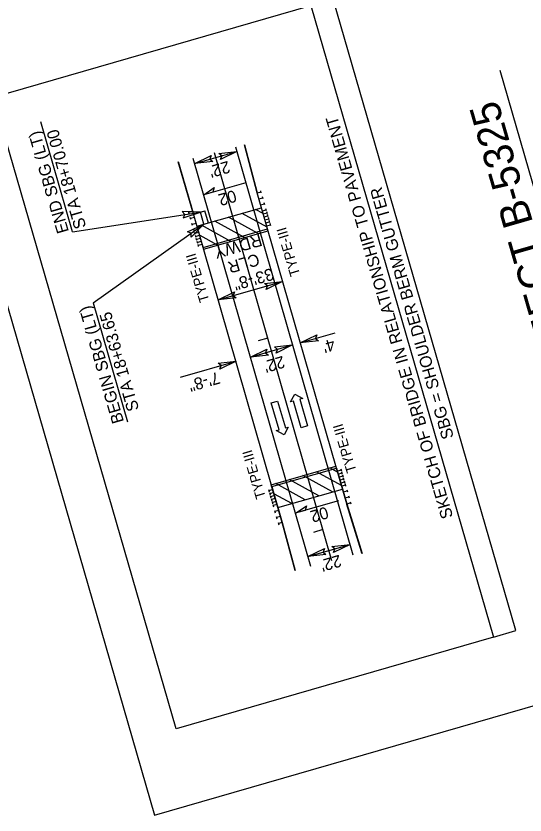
# Model space of a CAD drawing. Extents: x 2167182 to 2168576, y 842635 to 844493.
# Drawn here: x 2167498 to 2167753.4, y 842716.2 to 843117.4 of the extents above; entities that cross this region are included whole.
import ezdxf

# ---------------------------------------------------------------- set-up
doc = ezdxf.new("R2010")
doc.units = 0
for name, color, linetype in [('Old_Level_2', 7, 'Continuous'), ('Prop Approach Slab', 7, 'Continuous'), ('Prop Approach Slab Hatching', 7, 'Continuous'), ('Prop Conc Shoulder Berm Gutter', 7, 'Continuous'), ('Prop Dimension', 7, 'Continuous'), ('Prop Dimension Text', 7, 'Continuous'), ('Prop EOT', 7, 'Continuous'), ('Prop Guardrail', 7, 'Continuous'), ('Prop Horizontal Alignment', 7, 'Continuous'), ('Prop Horizontal Alignment Tick Small', 7, 'Continuous'), ('Prop Lane Arrow CELL', 7, 'Continuous'), ('Prop Paved Shoulder', 7, 'Continuous'), ('Prop Roadway Bridge', 7, 'Continuous'), ('Prop Structure Anchor Unit CELL', 7, 'Continuous'), ('Prop Superelevation  Arrow CELL', 7, 'Continuous'), ('Prop Superelevation Label', 7, 'Continuous'), ('Prop Terminator CELL', 7, 'Continuous'), ('Sheet Layout Plan Border', 7, 'Continuous')]:
    doc.layers.add(name, color=color, linetype=linetype)

msp = doc.modelspace()

# ---------------------------------------------------------------- linework, layer by layer
at = {"layer": 'Prop Approach Slab'}
for p, q in [((2167588.77, 843011.83), (2167621.12, 843021.13)), ((2167588.77, 843011.83), (2167592.08, 843000.29)), ((2167592.08, 843000.29), (2167624.44, 843009.6)), ((2167626.07, 842882.08), (2167658.43, 842891.39)), ((2167629.39, 842870.55), (2167626.07, 842882.08)), ((2167629.39, 842870.55), (2167661.75, 842879.85))]:
    msp.add_line(p, q, dxfattribs=at)
at = {"layer": 'Prop Approach Slab Hatching'}
for p, q in [((2167623.93, 843011.38), (2167611.37, 843018.33)), ((2167621.97, 843018.18), (2167618.17, 843020.28)), ((2167612.63, 843006.2), (2167597.78, 843014.42)), ((2167619.43, 843008.16), (2167604.58, 843016.37)), ((2167605.84, 843004.25), (2167590.99, 843012.46)), ((2167599.04, 843002.29), (2167590.29, 843007.13)), ((2167661.23, 842881.64), (2167648.68, 842888.58)), ((2167659.28, 842888.43), (2167655.48, 842890.54)), ((2167649.94, 842876.46), (2167635.09, 842884.68)), ((2167656.73, 842878.41), (2167641.89, 842886.63)), ((2167643.14, 842874.5), (2167628.29, 842882.72)), ((2167636.35, 842872.55), (2167627.6, 842877.39))]:
    msp.add_line(p, q, dxfattribs=at)
at = {"layer": 'Prop Conc Shoulder Berm Gutter'}
msp.add_line((2167592.29, 843012.84), (2167590.54, 843018.94), dxfattribs=at)
at = {"layer": 'Prop Dimension'}
for p, q in [((2167748.76, 842808.79), (2167657.06, 843125.98)), ((2167526.37, 843009.04), (2167510.4, 843064.31)), ((2167587.69, 843043.3), (2167608.84, 843049.38)), ((2167526.37, 843009.04), (2167590.54, 843018.94)), ((2167536.67, 842973.42), (2167592.29, 843012.84)), ((2167599.4, 842974.85), (2167631.76, 842984.15)), ((2167536.67, 842973.42), (2167553.95, 842913.65)), ((2167640.62, 842953.33), (2167658.16, 842958.37)), ((2167615.63, 842946.15), (2167636.77, 842952.23)), ((2167580.5, 842936.04), (2167608.42, 842944.07)), ((2167644.43, 842846), (2167665.57, 842852.08)), ((2167737.53, 842805.55), (2167748.76, 842808.79))]:
    msp.add_line(p, q, dxfattribs=at)
msp.add_lwpolyline([(2167578.27, 842759.51), (2167486.57, 843076.7), (2167645.84, 843122.74), (2167737.53, 842805.55)], close=True, dxfattribs=at)
msp.add_lwpolyline([(2168072.93, 842886.81), (2167822.86, 842806.27), (2167740.86, 843090.03)], dxfattribs=at)
at = {"layer": 'Prop EOT'}
for p, q in [((2167667.12, 842846.7), (2167608.2, 843051.59)), ((2167645.85, 842841.04), (2167586.94, 843045.93))]:
    msp.add_line(p, q, dxfattribs=at)
at = {"layer": 'Prop Guardrail'}
for p, q in [((2167618.98, 843028.58), (2167612.55, 843052.74)), ((2167631.53, 842863.1), (2167637.96, 842838.94))]:
    msp.add_line(p, q, dxfattribs=at)
for points in [[(2167579.35, 843044.25), (2167579.39, 843044.14), (2167579.42, 843044.03), (2167579.45, 843043.93), (2167579.51, 843043.71), (2167579.57, 843043.49), (2167579.64, 843043.28), (2167579.7, 843043.06), (2167579.76, 843042.84), (2167579.83, 843042.63), (2167579.89, 843042.41), (2167579.95, 843042.2), (2167580.01, 843041.98), (2167580.08, 843041.76), (2167580.14, 843041.55), (2167580.2, 843041.33), (2167580.27, 843041.11), (2167580.33, 843040.9), (2167580.39, 843040.68), (2167580.46, 843040.47), (2167580.52, 843040.25), (2167580.58, 843040.03), (2167580.64, 843039.82), (2167580.71, 843039.6), (2167580.77, 843039.38), (2167580.83, 843039.17), (2167580.9, 843038.95), (2167580.96, 843038.74), (2167581.02, 843038.52), (2167581.08, 843038.3), (2167581.15, 843038.09), (2167581.21, 843037.87), (2167581.27, 843037.65), (2167581.34, 843037.44), (2167581.4, 843037.22), (2167581.46, 843037.01), (2167581.53, 843036.79), (2167581.59, 843036.57), (2167581.65, 843036.36), (2167581.71, 843036.14), (2167581.78, 843035.92), (2167581.84, 843035.71), (2167581.9, 843035.49), (2167581.97, 843035.28), (2167582.03, 843035.06), (2167582.09, 843034.84), (2167582.16, 843034.63), (2167582.22, 843034.41), (2167582.28, 843034.19), (2167582.34, 843033.98), (2167582.41, 843033.76), (2167582.47, 843033.55), (2167582.53, 843033.33), (2167582.6, 843033.11), (2167582.66, 843032.9), (2167582.72, 843032.68), (2167582.78, 843032.46), (2167582.85, 843032.25), (2167582.91, 843032.03), (2167582.97, 843031.82), (2167583.04, 843031.6), (2167583.1, 843031.38), (2167583.16, 843031.17), (2167583.23, 843030.95), (2167583.29, 843030.73), (2167583.35, 843030.52), (2167583.41, 843030.3), (2167583.48, 843030.09), (2167583.54, 843029.87), (2167583.6, 843029.65), (2167583.67, 843029.44), (2167583.73, 843029.22), (2167583.79, 843029.01), (2167583.86, 843028.79), (2167583.92, 843028.57), (2167583.98, 843028.36), (2167584.04, 843028.14), (2167584.11, 843027.92), (2167584.17, 843027.71), (2167584.23, 843027.49), (2167584.3, 843027.28), (2167584.36, 843027.06), (2167584.42, 843026.84), (2167584.48, 843026.63), (2167584.55, 843026.41), (2167584.61, 843026.19), (2167584.67, 843025.98), (2167584.74, 843025.76), (2167584.8, 843025.55), (2167584.86, 843025.33), (2167584.93, 843025.11), (2167584.99, 843024.9), (2167585.05, 843024.68), (2167585.11, 843024.46), (2167585.18, 843024.25), (2167585.24, 843024.03), (2167585.3, 843023.82), (2167585.37, 843023.6), (2167585.43, 843023.38), (2167585.49, 843023.17), (2167585.56, 843022.95), (2167585.62, 843022.73), (2167585.68, 843022.52), (2167585.74, 843022.3), (2167585.81, 843022.09), (2167585.87, 843021.87), (2167585.93, 843021.65), (2167586, 843021.44), (2167586.06, 843021.22), (2167586.12, 843021), (2167586.18, 843020.79), (2167586.25, 843020.57), (2167586.37, 843020.14), (2167586.5, 843019.71), (2167586.63, 843019.27)], [(2167671.58, 842847.55), (2167671.54, 842847.66), (2167671.51, 842847.76), (2167671.48, 842847.87), (2167671.41, 842848.09), (2167671.34, 842848.3), (2167671.28, 842848.52), (2167671.21, 842848.73), (2167671.14, 842848.95), (2167671.08, 842849.17), (2167671.01, 842849.38), (2167670.94, 842849.6), (2167670.88, 842849.81), (2167670.81, 842850.03), (2167670.75, 842850.24), (2167670.68, 842850.46), (2167670.61, 842850.67), (2167670.55, 842850.89), (2167670.48, 842851.1), (2167670.41, 842851.32), (2167670.35, 842851.53), (2167670.28, 842851.75), (2167670.21, 842851.96), (2167670.15, 842852.18), (2167670.08, 842852.39), (2167670.01, 842852.61), (2167669.95, 842852.82), (2167669.88, 842853.04), (2167669.81, 842853.25), (2167669.75, 842853.47), (2167669.68, 842853.68), (2167669.61, 842853.9), (2167669.55, 842854.12), (2167669.48, 842854.33), (2167669.41, 842854.55), (2167669.35, 842854.76), (2167669.28, 842854.98), (2167669.21, 842855.19), (2167669.15, 842855.41), (2167669.08, 842855.62), (2167669.01, 842855.84), (2167668.95, 842856.05), (2167668.88, 842856.27), (2167668.81, 842856.48), (2167668.75, 842856.7), (2167668.68, 842856.91), (2167668.61, 842857.13), (2167668.55, 842857.34), (2167668.48, 842857.56), (2167668.42, 842857.77), (2167668.35, 842857.99), (2167668.28, 842858.2), (2167668.22, 842858.42), (2167668.15, 842858.63), (2167668.08, 842858.85), (2167668.02, 842859.06), (2167667.95, 842859.28), (2167667.88, 842859.5), (2167667.82, 842859.71), (2167667.75, 842859.93), (2167667.68, 842860.14), (2167667.62, 842860.36), (2167667.55, 842860.57), (2167667.48, 842860.79), (2167667.42, 842861), (2167667.35, 842861.22), (2167667.28, 842861.43), (2167667.22, 842861.65), (2167667.15, 842861.86), (2167667.08, 842862.08), (2167667.02, 842862.29), (2167666.95, 842862.51), (2167666.88, 842862.72), (2167666.82, 842862.94), (2167666.75, 842863.15), (2167666.68, 842863.37), (2167666.62, 842863.58), (2167666.55, 842863.8), (2167666.48, 842864.01), (2167666.42, 842864.23), (2167666.35, 842864.45), (2167666.28, 842864.66), (2167666.22, 842864.88), (2167666.15, 842865.09), (2167666.09, 842865.31), (2167666.02, 842865.52), (2167665.95, 842865.74), (2167665.89, 842865.95), (2167665.82, 842866.17), (2167665.75, 842866.38), (2167665.69, 842866.6), (2167665.62, 842866.81), (2167665.55, 842867.03), (2167665.49, 842867.24), (2167665.42, 842867.46), (2167665.35, 842867.67), (2167665.29, 842867.89), (2167665.22, 842868.1), (2167665.15, 842868.32), (2167665.09, 842868.53), (2167665.02, 842868.75), (2167664.95, 842868.96), (2167664.89, 842869.18), (2167664.82, 842869.39), (2167664.75, 842869.61), (2167664.69, 842869.83), (2167664.62, 842870.04), (2167664.55, 842870.26), (2167664.49, 842870.47), (2167664.42, 842870.69), (2167664.35, 842870.9), (2167664.29, 842871.12), (2167664.15, 842871.55), (2167664.02, 842871.98), (2167663.89, 842872.41)]]:
    msp.add_open_spline(points, degree=3, dxfattribs=at)
at = {"layer": 'Prop Horizontal Alignment'}
msp.add_line((2167656.49, 842843.87), (2167597.57, 843048.76), dxfattribs=at)
at = {"layer": 'Prop Horizontal Alignment Tick Small'}
for p, q in [((2167624.35, 842955.62), (2167619.55, 842954.24)), ((2167651.99, 842859.52), (2167647.18, 842858.14))]:
    msp.add_line(p, q, dxfattribs=at)
at = {"layer": 'Prop Lane Arrow CELL'}
for p, q in [((2167635.78, 842923.68), (2167637.89, 842927.57)), ((2167637.89, 842927.57), (2167641.84, 842925.43)), ((2167641.84, 842925.43), (2167640.4, 842925.02)), ((2167640.4, 842925.02), (2167644.28, 842911.57)), ((2167626.08, 842923.12), (2167629.25, 842924.04)), ((2167629.96, 842909.67), (2167626.08, 842923.12)), ((2167629.25, 842924.04), (2167633.13, 842910.59)), ((2167637.22, 842924.1), (2167635.78, 842923.68)), ((2167641.11, 842910.65), (2167637.22, 842924.1)), ((2167628.52, 842909.25), (2167629.96, 842909.67)), ((2167632.47, 842907.12), (2167628.52, 842909.25)), ((2167634.58, 842911), (2167632.47, 842907.12)), ((2167633.13, 842910.59), (2167634.58, 842911)), ((2167644.28, 842911.57), (2167641.11, 842910.65))]:
    msp.add_line(p, q, dxfattribs=at)
at = {"layer": 'Prop Paved Shoulder'}
for p, q in [((2167612.55, 843052.74), (2167618.98, 843028.58)), ((2167587.01, 843017.93), (2167579.35, 843044.25)), ((2167624.16, 843010.56), (2167618.98, 843028.58)), ((2167587.01, 843017.93), (2167592.78, 843019.59)), ((2167594.53, 843013.48), (2167592.78, 843019.59)), ((2167663.89, 842872.41), (2167658.71, 842890.43)), ((2167663.89, 842872.41), (2167671.58, 842847.55)), ((2167631.53, 842863.1), (2167629.39, 842870.55)), ((2167637.96, 842838.94), (2167631.53, 842863.1))]:
    msp.add_line(p, q, dxfattribs=at)
at = {"layer": 'Prop Roadway Bridge'}
for p, q in [((2167591.81, 843001.25), (2167624.16, 843010.56)), ((2167658.71, 842890.43), (2167624.16, 843010.56)), ((2167626.35, 842881.12), (2167591.81, 843001.25)), ((2167626.35, 842881.12), (2167658.71, 842890.43))]:
    msp.add_line(p, q, dxfattribs=at)
at = {"layer": 'Prop Structure Anchor Unit CELL'}
for p, q in [((2167618.98, 843028.58), (2167620.9, 843029.13)), ((2167621.06, 843028.58), (2167620.75, 843029.68)), ((2167624.16, 843010.56), (2167618.98, 843028.58)), ((2167619.84, 843025.57), (2167621.77, 843026.13)), ((2167621.93, 843025.58), (2167621.61, 843026.68)), ((2167620.71, 843022.57), (2167622.63, 843023.12)), ((2167622.79, 843022.57), (2167622.47, 843023.67)), ((2167584.86, 843018.17), (2167584.55, 843019.27)), ((2167586.63, 843019.27), (2167584.7, 843018.72)), ((2167591.81, 843001.25), (2167586.63, 843019.27)), ((2167621.57, 843019.57), (2167623.49, 843020.12)), ((2167622, 843018.07), (2167623.93, 843018.62)), ((2167622.44, 843016.56), (2167624.36, 843017.12)), ((2167623.65, 843019.57), (2167623.34, 843020.67)), ((2167624.08, 843018.07), (2167623.77, 843019.17)), ((2167624.52, 843016.57), (2167624.2, 843017.67)), ((2167585.73, 843015.17), (2167585.41, 843016.27)), ((2167587.49, 843016.27), (2167585.57, 843015.72)), ((2167586.59, 843012.16), (2167586.27, 843013.27)), ((2167588.35, 843013.27), (2167586.43, 843012.71)), ((2167622.87, 843015.06), (2167624.79, 843015.62)), ((2167623.3, 843013.56), (2167625.22, 843014.11)), ((2167624.95, 843015.07), (2167624.63, 843016.17)), ((2167625.38, 843013.56), (2167625.06, 843014.66)), ((2167625.81, 843012.06), (2167625.49, 843013.16)), ((2167587.45, 843009.16), (2167587.14, 843010.26)), ((2167589.22, 843010.26), (2167587.29, 843009.71)), ((2167623.73, 843012.06), (2167625.65, 843012.61)), ((2167587.88, 843007.66), (2167587.57, 843008.76)), ((2167589.65, 843008.76), (2167587.73, 843008.21)), ((2167588.32, 843006.16), (2167588, 843007.26)), ((2167590.08, 843007.26), (2167588.16, 843006.71)), ((2167588.75, 843004.66), (2167588.43, 843005.76)), ((2167590.51, 843005.76), (2167588.59, 843005.21)), ((2167589.18, 843003.15), (2167588.86, 843004.26)), ((2167590.94, 843004.26), (2167589.02, 843003.7)), ((2167589.61, 843001.65), (2167589.29, 843002.75)), ((2167591.38, 843002.76), (2167589.45, 843002.2)), ((2167658.71, 842890.43), (2167663.89, 842872.41)), ((2167659.14, 842888.92), (2167661.06, 842889.48)), ((2167660.9, 842890.03), (2167661.22, 842888.93)), ((2167661.33, 842888.53), (2167661.65, 842887.43)), ((2167659.57, 842887.42), (2167661.49, 842887.98)), ((2167660, 842885.92), (2167661.92, 842886.47)), ((2167660.43, 842884.42), (2167662.36, 842884.97)), ((2167661.77, 842887.02), (2167662.08, 842885.92)), ((2167662.2, 842885.52), (2167662.51, 842884.42)), ((2167626.35, 842881.12), (2167631.53, 842863.1)), ((2167660.87, 842882.92), (2167662.79, 842883.47)), ((2167661.3, 842881.42), (2167663.22, 842881.97)), ((2167662.63, 842884.02), (2167662.95, 842882.92)), ((2167663.06, 842882.52), (2167663.38, 842881.42)), ((2167624.7, 842879.62), (2167625.02, 842878.52)), ((2167626.78, 842879.62), (2167624.86, 842879.07)), ((2167625.13, 842878.12), (2167625.45, 842877.02)), ((2167627.21, 842878.12), (2167625.29, 842877.57)), ((2167625.57, 842876.61), (2167625.88, 842875.51)), ((2167627.65, 842876.62), (2167625.72, 842876.06)), ((2167662.16, 842878.41), (2167664.08, 842878.97)), ((2167663.93, 842879.52), (2167664.24, 842878.42)), ((2167664.79, 842876.51), (2167665.11, 842875.41)), ((2167626, 842875.11), (2167626.31, 842874.01)), ((2167628.08, 842875.12), (2167626.16, 842874.56)), ((2167626.43, 842873.61), (2167626.75, 842872.51)), ((2167628.51, 842873.61), (2167626.59, 842873.06)), ((2167663.03, 842875.41), (2167664.95, 842875.96)), ((2167663.89, 842872.41), (2167665.81, 842872.96)), ((2167665.65, 842873.51), (2167665.97, 842872.41)), ((2167626.86, 842872.11), (2167627.18, 842871.01)), ((2167628.94, 842872.11), (2167627.02, 842871.56)), ((2167627.73, 842869.11), (2167628.04, 842868.01)), ((2167629.81, 842869.11), (2167627.88, 842868.56)), ((2167628.59, 842866.1), (2167628.91, 842865)), ((2167630.67, 842866.11), (2167628.75, 842865.55)), ((2167629.45, 842863.1), (2167629.77, 842862)), ((2167631.53, 842863.1), (2167629.61, 842862.55))]:
    msp.add_line(p, q, dxfattribs=at)
at = {"layer": 'Prop Superelevation  Arrow CELL'}
for p, q in [((2167613.35, 843033.72), (2167592.21, 843027.64)), ((2167659.73, 842873.98), (2167638.58, 842867.9))]:
    msp.add_line(p, q, dxfattribs=at)
for points in [[(2167592.21, 843027.64), (2167597.42, 843031.23), (2167596.66, 843028.92)], [(2167638.58, 842867.9), (2167643.8, 842871.48), (2167643.03, 842869.18)]]:
    msp.add_lwpolyline(points, close=True, dxfattribs=at)
at = {"layer": 'Prop Terminator CELL'}
for points in [[(2167599.76, 843048.39), (2167608.84, 843049.38), (2167600.58, 843045.35), (2167601.24, 843047.2)], [(2167596.77, 843044.3), (2167587.69, 843043.3), (2167595.95, 843047.34), (2167595.29, 843045.49)], [(2167581.86, 843016.08), (2167590.54, 843018.94), (2167581.35, 843019.19), (2167582.72, 843017.78)], [(2167584.02, 843008.97), (2167592.29, 843012.84), (2167585.78, 843006.35), (2167585.81, 843008.32)], [(2167622.68, 842983.15), (2167631.76, 842984.15), (2167623.5, 842980.11), (2167624.16, 842981.97)], [(2167608.48, 842975.85), (2167599.4, 842974.85), (2167607.66, 842978.89), (2167606.99, 842977.03)], [(2167649.7, 842954.33), (2167640.62, 842953.33), (2167648.87, 842957.37), (2167648.21, 842955.51)], [(2167624.71, 842947.14), (2167615.63, 842946.15), (2167623.89, 842950.18), (2167623.22, 842948.33)], [(2167627.7, 842951.23), (2167636.77, 842952.23), (2167628.52, 842948.19), (2167629.18, 842950.04)], [(2167599.35, 842943.08), (2167608.42, 842944.07), (2167600.17, 842940.03), (2167600.83, 842941.89)], [(2167653.51, 842847), (2167644.43, 842846), (2167652.68, 842850.04), (2167652.02, 842848.18)], [(2167656.49, 842851.08), (2167665.57, 842852.08), (2167657.32, 842848.04), (2167657.98, 842849.9)]]:
    msp.add_lwpolyline(points, close=True, dxfattribs=at)
at = {"layer": 'Sheet Layout Plan Border'}
msp.add_lwpolyline([(2168191.21, 844341.01), (2167182.42, 844049.75), (2167182.42, 844049.75), (2167567.43, 842716.21), (2168576.23, 843007.46)], close=True, dxfattribs=at)

# ---------------------------------------------------------------- texts
at = {"layer": 'Old_Level_2'}
msp.add_text('BEGIN TIP PROJECT B-5325', height=15, rotation=106.1263, dxfattribs=at).set_placement((2167814.18, 842817.73))
at = {"layer": 'Prop Dimension Text'}
for s, rotation, p in [('SKETCH OF BRIDGE IN RELATIONSHIP TO PAVEMENT', 106.1263, (2167717.35, 842865.94)), ('END SBG (LT)', 106.1263, (2167524.55, 843009.25)), ('STA 18+70.00', 106.1263, (2167533.26, 843011.52)), ("22'", 196.0427, (2167604.36, 843044.75)), ('SBG = SHOULDER BERM GUTTER', 106.1263, (2167717.72, 842905.91)), ('RDWY', 196.0427, (2167620.38, 843007.98)), ('CLR', 196.0427, (2167619.14, 842998.26)), ('33\'-8"', 196.0427, (2167626.21, 842990.92)), ('BEGIN SBG (LT)', 106.1263, (2167552.19, 842913.78)), ('STA 18+63.65', 106.1263, (2167559.79, 842919.9)), ("4'", 196.0427, (2167657.02, 842955.55)), ("22'", 196.0427, (2167631.85, 842946.85)), ('7\'-8"', 196.0427, (2167599.31, 842938.84)), ("22'", 196.0427, (2167660.25, 842846.97))]:
    msp.add_text(s, height=6, rotation=rotation, dxfattribs=at).set_placement(p)
at = {"layer": 'Prop Structure Anchor Unit CELL'}
for p in [(2167640.56, 842987.6), (2167595.05, 842974.49), (2167668.87, 842888.9), (2167623.36, 842875.79)]:
    msp.add_text('TYPE-III', height=5, rotation=106.5508, dxfattribs=at).set_placement(p)
at = {"layer": 'Prop Superelevation Label'}
for p in [(2167607.54, 843030.16), (2167653.69, 842871.17)]:
    msp.add_text('02', height=6, rotation=196.0427, dxfattribs=at).set_placement(p)

doc.saveas('drawing.dxf')
